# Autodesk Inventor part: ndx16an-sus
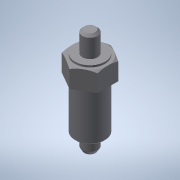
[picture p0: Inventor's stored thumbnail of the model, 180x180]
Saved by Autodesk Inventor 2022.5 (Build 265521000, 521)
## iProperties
Created: 2016-12
Part Number: ndx16an-sus
Material: 一般
Document SubType Name: Modeling
Designer: imaocorp
Density: 1 g/cm^3
Appearance: 既定
Author: imaocorp
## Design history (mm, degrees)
node "ndx16an-sus.x_t1"
node "ndx16an-sus"
node "Base1"
